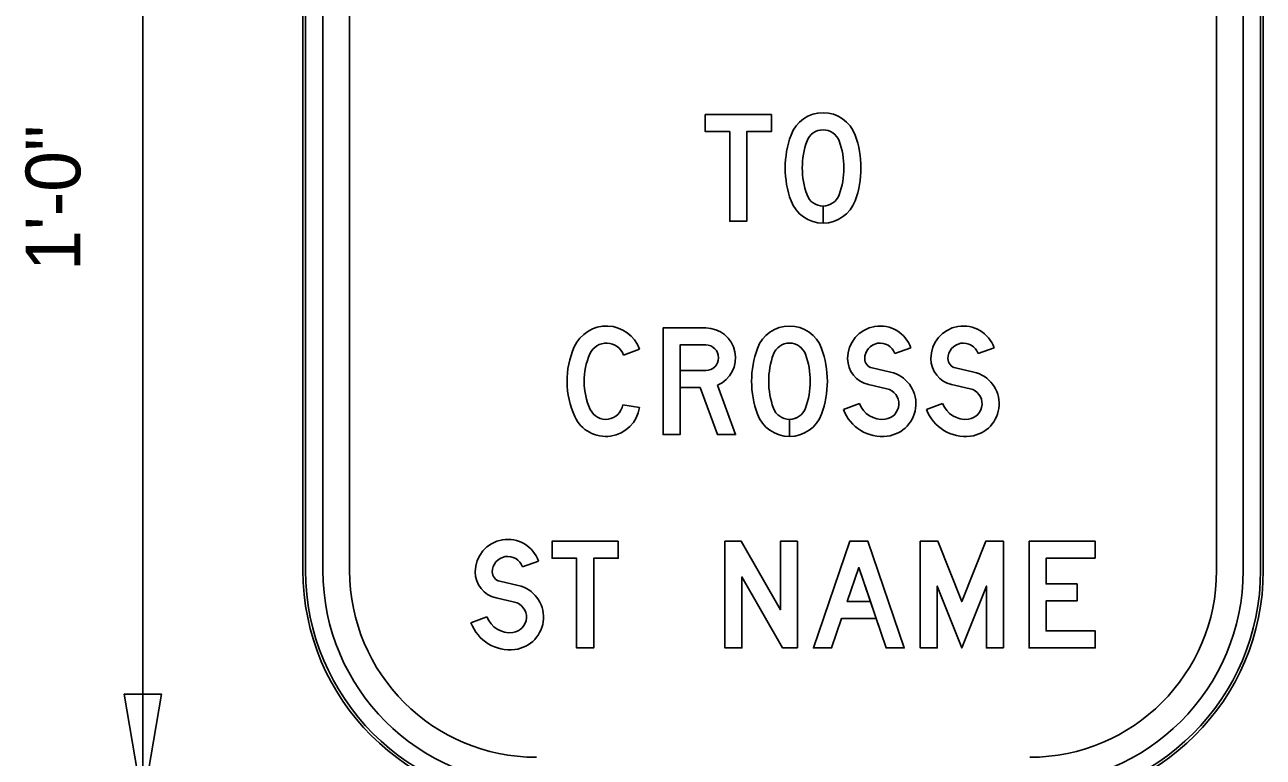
# Model space of a CAD drawing. Extents: x 0 to 770, y 0 to 495.
# Drawn here: x 44.3 to 123.4, y 393.3 to 440.1 of the extents above; entities that cross this region are included whole.
import ezdxf

# ---------------------------------------------------------------- set-up
doc = ezdxf.new("R2010")
doc.units = 0
for name, color, linetype in [('Dimension', 7, 'Continuous'), ('GSBWFill', 7, 'Continuous'), ('GSColorFill', 7, 'Continuous'), ('GSDims', 7, 'Continuous'), ('GSOutline', 7, 'Continuous'), ('TextStructures', 7, 'Continuous')]:
    doc.layers.add(name, color=color, linetype=linetype)

msp = doc.modelspace()

# ---------------------------------------------------------------- linework, layer by layer
at = {"layer": 'Dimension'}
msp.add_lwpolyline([(51.865, 390.366), (53.054, 397.382), (50.676, 397.382)], close=True, dxfattribs=at)
at = {"layer": 'GSBWFill'}
for p, q in [((62.087, 457.236), (62.087, 405.273)), ((63.365, 457.236), (63.365, 405.273)), ((65.069, 405.273), (65.069, 457.236)), ((120.439, 457.236), (120.439, 405.273)), ((122.143, 405.273), (122.143, 457.236)), ((123.42, 405.273), (123.42, 457.236)), ((95.309, 428.563), (95.309, 427.473)), ((95.31, 427.473), (95.31, 428.563)), ((83.588, 419.418), (82.563, 419.044)), ((86.178, 419.687), (87.813, 419.687)), ((99.889, 419.142), (100.919, 419.499)), ((105.204, 419.142), (106.234, 419.499)), ((99.621, 417.952), (98.445, 418.22)), ((104.936, 417.952), (103.76, 418.22)), ((98.203, 417.157), (99.379, 416.889)), ((103.518, 417.157), (104.694, 416.889)), ((82.51, 415.863), (83.588, 415.702)), ((97.625, 415.948), (96.604, 415.564)), ((102.94, 415.948), (101.92, 415.564)), ((93.163, 413.843), (93.163, 414.933)), ((93.163, 414.933), (93.163, 413.843)), ((76.105, 405.512), (77.135, 405.87)), ((75.837, 404.323), (74.661, 404.59)), ((74.419, 403.527), (75.595, 403.26)), ((73.841, 402.319), (72.821, 401.934))]:
    msp.add_line(p, q, dxfattribs=at)
for points in [[(92.004, 434.407), (92.004, 433.316), (90.437, 433.316), (90.437, 427.592), (89.346, 427.592), (89.346, 433.316), (87.779, 433.316), (87.779, 434.407)], [(82.225, 407.148), (82.225, 406.057), (80.658, 406.057), (80.658, 400.333), (79.567, 400.333), (79.567, 406.057), (78, 406.057), (78, 407.148)], [(93.674, 400.333), (93.674, 407.148), (92.583, 407.148), (92.583, 402.769), (90.081, 407.148), (89.04, 407.148), (89.04, 400.333), (90.13, 400.333), (90.13, 404.865), (92.72, 400.333)], [(94.696, 400.333), (97.013, 407.148), (98.172, 407.148), (100.489, 400.333), (99.337, 400.333), (97.592, 405.464), (96.855, 403.297), (98.329, 403.297), (98.7, 402.206), (96.485, 402.206), (95.848, 400.333)], [(106.826, 400.333), (106.826, 407.148), (105.698, 407.148), (104.169, 403.291), (102.639, 407.148), (101.511, 407.148), (101.511, 400.333), (102.601, 400.333), (102.601, 404.285), (104.169, 400.333), (105.736, 404.285), (105.736, 400.333)], [(112.687, 406.057), (109.552, 406.057), (109.552, 404.422), (111.534, 404.422), (111.534, 403.331), (109.552, 403.331), (109.552, 401.423), (112.687, 401.423), (112.687, 400.333), (108.462, 400.333), (108.462, 407.148), (112.687, 407.148)]]:
    msp.add_lwpolyline(points, close=True, dxfattribs=at)
for points in [[(87.813, 420.777), (85.087, 420.777), (85.087, 413.962), (86.178, 413.962), (86.178, 419.687)], [(87.813, 418.051), (86.178, 418.051), (86.178, 416.961), (87.457, 416.961), (88.56, 413.962), (89.721, 413.962), (88.563, 417.114)]]:
    msp.add_lwpolyline(points, dxfattribs=at)
for centre, radius, start, end in [((81.475, 418.647), 2.249, 20.02358, 155.94529), ((98.955, 418.818), 2.079, 19.13948, 180), ((104.271, 418.818), 2.079, 19.13948, 180), ((87.813, 418.869), 1.908, 293.1324, 90), ((84.338, 417.37), 5.384, 155.9453, 204.84802), ((81.475, 418.647), 1.159, 20.02358, 155.94529), ((87.813, 418.869), 0.818, 270, 90), ((98.955, 418.818), 0.988, 19.13948, 180), ((104.271, 418.818), 0.988, 19.13948, 180), ((84.338, 417.37), 4.293, 155.94529, 204.84802), ((98.58, 418.818), 1.704, 180, 257.19149), ((98.58, 418.818), 0.613, 180, 257.19149), ((103.896, 418.818), 1.704, 180, 257.19149), ((103.896, 418.818), 0.613, 180, 257.19149), ((99.16, 415.926), 2.079, 276.78539, 77.19149), ((104.475, 415.926), 2.079, 276.78539, 77.19149), ((99.16, 415.926), 0.988, 276.78539, 77.19149), ((104.475, 415.926), 0.988, 276.78539, 77.19149), ((81.431, 416.024), 2.181, 204.84802, 351.50601), ((81.431, 416.024), 1.09, 204.84802, 351.50601), ((99.091, 416.501), 2.658, 200.64423, 276.78539), ((99.091, 416.501), 1.567, 200.64423, 276.78539), ((104.407, 416.501), 2.658, 200.64423, 276.78539), ((104.407, 416.501), 1.567, 200.64423, 276.78539), ((75.172, 405.188), 2.079, 19.13948, 180), ((75.172, 405.188), 0.988, 19.13948, 180), ((76.995, 405.273), 14.907, 180, 270), ((76.995, 405.273), 13.63, 180, 270), ((76.995, 405.273), 11.926, 180, 270), ((74.797, 405.188), 1.704, 180, 257.19149), ((74.797, 405.188), 0.613, 180, 257.19149), ((108.513, 405.273), 13.63, 270, 0), ((108.513, 405.273), 11.926, 270, 0), ((108.513, 405.273), 14.907, 270, 0), ((75.376, 402.296), 2.079, 276.78539, 77.19149), ((75.376, 402.296), 0.988, 276.78539, 77.19149), ((75.308, 402.871), 2.658, 200.64423, 276.78539), ((75.308, 402.871), 1.567, 200.64423, 276.78539)]:
    msp.add_arc(centre, radius, start, end, dxfattribs=at)
for centre, major_axis, start_param, end_param in [((95.309, 432.345), (0, 2.181), 5.063177, 7.503193), ((98.987, 430.999), (0, 6.097), 1.220008, 1.921585), ((98.987, 430.999), (0, 5.007), 1.220008, 1.921585), ((95.309, 432.345), (0, 1.09), 5.063177, 7.503193), ((91.631, 430.999), (0, 5.007), 4.361601, 5.063177), ((91.631, 430.999), (0, 6.097), 4.361601, 5.063177), ((95.309, 429.653), (0, 2.181), 1.921585, 3.141593), ((95.309, 429.653), (0, 1.09), 1.921585, 3.141593), ((95.309, 429.653), (0, 1.09), 3.141905, 4.361601), ((95.309, 429.653), (0, 2.181), 3.141749, 4.361601), ((93.163, 418.716), (0, 2.181), 5.063177, 7.503193), ((96.841, 417.37), (0, 6.097), 1.220008, 1.921585), ((93.163, 418.716), (0, 1.09), 5.063177, 7.503193), ((89.485, 417.37), (0, 6.097), 4.361601, 5.063177), ((96.841, 417.37), (0, 5.007), 1.220008, 1.921585), ((89.485, 417.37), (0, 5.007), 4.361601, 5.063177), ((93.163, 416.024), (0, 2.181), 1.921585, 3.141593), ((93.163, 416.024), (0, 1.09), 1.921585, 3.141593), ((93.163, 416.024), (0, 1.09), 3.141905, 4.361601), ((93.163, 416.024), (0, 2.181), 3.141749, 4.361601)]:
    msp.add_ellipse(centre, major_axis=major_axis, ratio=0.999993, start_param=start_param, end_param=end_param, dxfattribs=at)
at = {"layer": 'GSColorFill'}
for p, q in [((62.087, 457.236), (62.087, 405.273)), ((62.087, 457.236), (62.087, 405.273)), ((62.258, 405.273), (62.258, 457.236)), ((63.365, 457.236), (63.365, 405.273)), ((65.069, 405.273), (65.069, 457.236)), ((120.439, 457.236), (120.439, 405.273)), ((122.143, 405.273), (122.143, 457.236)), ((123.25, 457.236), (123.25, 405.273)), ((123.42, 405.273), (123.42, 457.236)), ((123.42, 405.273), (123.42, 457.236)), ((95.309, 428.563), (95.309, 427.473)), ((95.31, 427.473), (95.31, 428.563)), ((83.588, 419.418), (82.563, 419.044)), ((86.178, 419.687), (87.813, 419.687)), ((99.889, 419.142), (100.919, 419.499)), ((105.204, 419.142), (106.234, 419.499)), ((99.621, 417.952), (98.445, 418.22)), ((104.936, 417.952), (103.76, 418.22)), ((98.203, 417.157), (99.379, 416.889)), ((103.518, 417.157), (104.694, 416.889)), ((82.51, 415.863), (83.588, 415.702)), ((97.625, 415.948), (96.604, 415.564)), ((102.94, 415.948), (101.92, 415.564)), ((93.163, 413.843), (93.163, 414.933)), ((93.163, 414.933), (93.163, 413.843)), ((76.105, 405.512), (77.135, 405.87)), ((75.837, 404.323), (74.661, 404.59)), ((74.419, 403.527), (75.595, 403.26)), ((73.841, 402.319), (72.821, 401.934))]:
    msp.add_line(p, q, dxfattribs=at)
for points in [[(92.004, 434.407), (92.004, 433.316), (90.437, 433.316), (90.437, 427.592), (89.346, 427.592), (89.346, 433.316), (87.779, 433.316), (87.779, 434.407)], [(82.225, 407.148), (82.225, 406.057), (80.658, 406.057), (80.658, 400.333), (79.567, 400.333), (79.567, 406.057), (78, 406.057), (78, 407.148)], [(93.674, 400.333), (93.674, 407.148), (92.583, 407.148), (92.583, 402.769), (90.081, 407.148), (89.04, 407.148), (89.04, 400.333), (90.13, 400.333), (90.13, 404.865), (92.72, 400.333)], [(94.696, 400.333), (97.013, 407.148), (98.172, 407.148), (100.489, 400.333), (99.337, 400.333), (97.592, 405.464), (96.855, 403.297), (98.329, 403.297), (98.7, 402.206), (96.485, 402.206), (95.848, 400.333)], [(106.826, 400.333), (106.826, 407.148), (105.698, 407.148), (104.169, 403.291), (102.639, 407.148), (101.511, 407.148), (101.511, 400.333), (102.601, 400.333), (102.601, 404.285), (104.169, 400.333), (105.736, 404.285), (105.736, 400.333)], [(112.687, 406.057), (109.552, 406.057), (109.552, 404.422), (111.534, 404.422), (111.534, 403.331), (109.552, 403.331), (109.552, 401.423), (112.687, 401.423), (112.687, 400.333), (108.462, 400.333), (108.462, 407.148), (112.687, 407.148)]]:
    msp.add_lwpolyline(points, close=True, dxfattribs=at)
for points in [[(87.813, 420.777), (85.087, 420.777), (85.087, 413.962), (86.178, 413.962), (86.178, 419.687)], [(87.813, 418.051), (86.178, 418.051), (86.178, 416.961), (87.457, 416.961), (88.56, 413.962), (89.721, 413.962), (88.563, 417.114)]]:
    msp.add_lwpolyline(points, dxfattribs=at)
for centre, radius, start, end in [((81.475, 418.647), 2.249, 20.02358, 155.94529), ((98.955, 418.818), 2.079, 19.13948, 180), ((104.271, 418.818), 2.079, 19.13948, 180), ((87.813, 418.869), 1.908, 293.1324, 90), ((84.338, 417.37), 5.384, 155.9453, 204.84802), ((81.475, 418.647), 1.159, 20.02358, 155.94529), ((87.813, 418.869), 0.818, 270, 90), ((98.955, 418.818), 0.988, 19.13948, 180), ((104.271, 418.818), 0.988, 19.13948, 180), ((84.338, 417.37), 4.293, 155.94529, 204.84802), ((98.58, 418.818), 1.704, 180, 257.19149), ((98.58, 418.818), 0.613, 180, 257.19149), ((103.896, 418.818), 1.704, 180, 257.19149), ((103.896, 418.818), 0.613, 180, 257.19149), ((99.16, 415.926), 2.079, 276.78539, 77.19149), ((104.475, 415.926), 2.079, 276.78539, 77.19149), ((99.16, 415.926), 0.988, 276.78539, 77.19149), ((104.475, 415.926), 0.988, 276.78539, 77.19149), ((81.431, 416.024), 2.181, 204.84802, 351.50601), ((81.431, 416.024), 1.09, 204.84802, 351.50601), ((99.091, 416.501), 2.658, 200.64423, 276.78539), ((99.091, 416.501), 1.567, 200.64423, 276.78539), ((104.407, 416.501), 2.658, 200.64423, 276.78539), ((104.407, 416.501), 1.567, 200.64423, 276.78539), ((75.172, 405.188), 2.079, 19.13948, 180), ((75.172, 405.188), 0.988, 19.13948, 180), ((76.995, 405.273), 14.907, 180, 270), ((76.995, 405.273), 14.907, 180, 270), ((76.995, 405.273), 14.737, 180, 270), ((76.995, 405.273), 13.63, 180, 270), ((76.995, 405.273), 11.926, 180, 270), ((74.797, 405.188), 1.704, 180, 257.19149), ((74.797, 405.188), 0.613, 180, 257.19149), ((108.513, 405.273), 14.907, 270, 0), ((108.513, 405.273), 13.63, 270, 0), ((108.513, 405.273), 11.926, 270, 0), ((108.513, 405.273), 14.907, 270, 0), ((108.513, 405.273), 14.737, 270, 0), ((75.376, 402.296), 2.079, 276.78539, 77.19149), ((75.376, 402.296), 0.988, 276.78539, 77.19149), ((75.308, 402.871), 2.658, 200.64423, 276.78539), ((75.308, 402.871), 1.567, 200.64423, 276.78539)]:
    msp.add_arc(centre, radius, start, end, dxfattribs=at)
for centre, major_axis, start_param, end_param in [((95.309, 432.345), (0, 2.181), 5.063177, 7.503193), ((98.987, 430.999), (0, 6.097), 1.220008, 1.921585), ((98.987, 430.999), (0, 5.007), 1.220008, 1.921585), ((95.309, 432.345), (0, 1.09), 5.063177, 7.503193), ((91.631, 430.999), (0, 5.007), 4.361601, 5.063177), ((91.631, 430.999), (0, 6.097), 4.361601, 5.063177), ((95.309, 429.653), (0, 2.181), 1.921585, 3.141593), ((95.309, 429.653), (0, 1.09), 1.921585, 3.141593), ((95.309, 429.653), (0, 1.09), 3.141905, 4.361601), ((95.309, 429.653), (0, 2.181), 3.141749, 4.361601), ((93.163, 418.716), (0, 2.181), 5.063177, 7.503193), ((96.841, 417.37), (0, 6.097), 1.220008, 1.921585), ((93.163, 418.716), (0, 1.09), 5.063177, 7.503193), ((89.485, 417.37), (0, 6.097), 4.361601, 5.063177), ((96.841, 417.37), (0, 5.007), 1.220008, 1.921585), ((89.485, 417.37), (0, 5.007), 4.361601, 5.063177), ((93.163, 416.024), (0, 2.181), 1.921585, 3.141593), ((93.163, 416.024), (0, 1.09), 1.921585, 3.141593), ((93.163, 416.024), (0, 1.09), 3.141905, 4.361601), ((93.163, 416.024), (0, 2.181), 3.141749, 4.361601)]:
    msp.add_ellipse(centre, major_axis=major_axis, ratio=0.999993, start_param=start_param, end_param=end_param, dxfattribs=at)
at = {"layer": 'GSDims'}
msp.add_line((51.865, 390.366), (51.865, 472.144), dxfattribs=at)
at = {"layer": 'GSOutline'}
for p, q in [((62.087, 457.236), (62.087, 405.273)), ((63.365, 457.236), (63.365, 405.273)), ((65.069, 457.236), (65.069, 405.273)), ((120.439, 405.273), (120.439, 457.236)), ((122.143, 405.273), (122.143, 457.236)), ((123.42, 405.273), (123.42, 457.236)), ((83.588, 419.418), (82.563, 419.044)), ((99.889, 419.142), (100.919, 419.499)), ((105.204, 419.142), (106.234, 419.499)), ((99.621, 417.952), (98.445, 418.22)), ((104.936, 417.952), (103.76, 418.22)), ((89.721, 413.962), (88.563, 417.114)), ((98.203, 417.157), (99.379, 416.889)), ((103.518, 417.157), (104.694, 416.889)), ((82.51, 415.863), (83.588, 415.702)), ((97.625, 415.948), (96.604, 415.564)), ((102.94, 415.948), (101.92, 415.564)), ((76.105, 405.512), (77.135, 405.87)), ((75.837, 404.323), (74.661, 404.59)), ((74.419, 403.527), (75.595, 403.26)), ((73.841, 402.319), (72.821, 401.934))]:
    msp.add_line(p, q, dxfattribs=at)
for points in [[(92.004, 434.407), (92.004, 433.316), (90.437, 433.316), (90.437, 427.592), (89.346, 427.592), (89.346, 433.316), (87.779, 433.316), (87.779, 434.407)], [(82.225, 407.148), (82.225, 406.057), (80.658, 406.057), (80.658, 400.333), (79.567, 400.333), (79.567, 406.057), (78, 406.057), (78, 407.148)], [(93.674, 400.333), (93.674, 407.148), (92.583, 407.148), (92.583, 402.769), (90.081, 407.148), (89.04, 407.148), (89.04, 400.333), (90.13, 400.333), (90.13, 404.865), (92.72, 400.333)], [(96.485, 402.206), (95.848, 400.333), (94.696, 400.333), (97.013, 407.148), (98.172, 407.148), (100.489, 400.333), (99.337, 400.333), (98.7, 402.206)], [(106.826, 400.333), (106.826, 407.148), (105.698, 407.148), (104.169, 403.291), (102.639, 407.148), (101.511, 407.148), (101.511, 400.333), (102.601, 400.333), (102.601, 404.285), (104.169, 400.333), (105.736, 404.285), (105.736, 400.333)], [(112.687, 406.057), (109.552, 406.057), (109.552, 404.422), (111.534, 404.422), (111.534, 403.331), (109.552, 403.331), (109.552, 401.423), (112.687, 401.423), (112.687, 400.333), (108.462, 400.333), (108.462, 407.148), (112.687, 407.148)], [(96.855, 403.297), (98.329, 403.297), (97.592, 405.464)]]:
    msp.add_lwpolyline(points, close=True, dxfattribs=at)
for points in [[(87.813, 420.777), (85.087, 420.777), (85.087, 413.962), (86.178, 413.962), (86.178, 416.961), (87.457, 416.961), (88.56, 413.962), (89.721, 413.962)], [(87.813, 418.051), (86.178, 418.051), (86.178, 419.687), (87.813, 419.687)]]:
    msp.add_lwpolyline(points, dxfattribs=at)
for centre, radius, start, end in [((81.475, 418.647), 2.249, 20.02358, 155.94529), ((98.955, 418.818), 2.079, 19.13948, 180), ((104.271, 418.818), 2.079, 19.13948, 180), ((87.813, 418.869), 1.908, 293.1324, 90), ((84.338, 417.37), 5.384, 155.9453, 204.84802), ((81.475, 418.647), 1.159, 20.02358, 155.94529), ((87.813, 418.869), 0.818, 270, 90), ((98.955, 418.818), 0.988, 19.13948, 180), ((104.271, 418.818), 0.988, 19.13948, 180), ((84.338, 417.37), 4.293, 155.94529, 204.84802), ((98.58, 418.818), 1.704, 180, 257.19149), ((98.58, 418.818), 0.613, 180, 257.19149), ((103.896, 418.818), 1.704, 180, 257.19149), ((103.896, 418.818), 0.613, 180, 257.19149), ((99.16, 415.926), 2.079, 276.78539, 77.19149), ((104.475, 415.926), 2.079, 276.78539, 77.19149), ((99.16, 415.926), 0.988, 276.78539, 77.19149), ((104.475, 415.926), 0.988, 276.78539, 77.19149), ((81.431, 416.024), 2.181, 204.84802, 351.50601), ((81.431, 416.024), 1.09, 204.84802, 351.50601), ((99.091, 416.501), 2.658, 200.64423, 276.78539), ((99.091, 416.501), 1.567, 200.64423, 276.78539), ((104.407, 416.501), 2.658, 200.64423, 276.78539), ((104.407, 416.501), 1.567, 200.64423, 276.78539), ((75.172, 405.188), 2.079, 19.13948, 180), ((75.172, 405.188), 0.988, 19.13948, 180), ((76.995, 405.273), 14.907, 180, 270), ((76.995, 405.273), 13.63, 180, 270), ((76.995, 405.273), 11.926, 180, 270), ((74.797, 405.188), 1.704, 180, 257.19149), ((74.797, 405.188), 0.613, 180, 257.19149), ((108.513, 405.273), 13.63, 270, 0), ((108.513, 405.273), 11.926, 270, 0), ((108.513, 405.273), 14.907, 270, 0), ((75.376, 402.296), 2.079, 276.78539, 77.19149), ((75.376, 402.296), 0.988, 276.78539, 77.19149), ((75.308, 402.871), 2.658, 200.64423, 276.78539), ((75.308, 402.871), 1.567, 200.64423, 276.78539)]:
    msp.add_arc(centre, radius, start, end, dxfattribs=at)
for centre, major_axis, start_param, end_param in [((95.309, 432.345), (0, 2.181), 5.063177, 7.503193), ((98.987, 430.999), (0, 6.097), 1.220008, 1.921585), ((98.987, 430.999), (0, 5.007), 1.220008, 1.921585), ((95.309, 432.345), (0, 1.09), 5.063177, 7.503193), ((91.631, 430.999), (0, 5.007), 4.361601, 5.063177), ((91.631, 430.999), (0, 6.097), 4.361601, 5.063177), ((95.309, 429.653), (0, 2.181), 1.921585, 4.361601), ((95.309, 429.653), (0, 1.09), 1.921585, 4.361601), ((93.163, 418.716), (0, 2.181), 5.063177, 7.503193), ((96.841, 417.37), (0, 6.097), 1.220008, 1.921585), ((93.163, 418.716), (0, 1.09), 5.063177, 7.503193), ((89.485, 417.37), (0, 6.097), 4.361601, 5.063177), ((96.841, 417.37), (0, 5.007), 1.220008, 1.921585), ((89.485, 417.37), (0, 5.007), 4.361601, 5.063177), ((93.163, 416.024), (0, 2.181), 1.921585, 4.361601), ((93.163, 416.024), (0, 1.09), 1.921585, 4.361601)]:
    msp.add_ellipse(centre, major_axis=major_axis, ratio=0.999993, start_param=start_param, end_param=end_param, dxfattribs=at)

# ---------------------------------------------------------------- texts
at = {"layer": 'TextStructures'}
msp.add_text('1\'-0"', height=3.5, rotation=90, dxfattribs=at).set_placement((47.874, 424.418))

doc.saveas('drawing.dxf')
